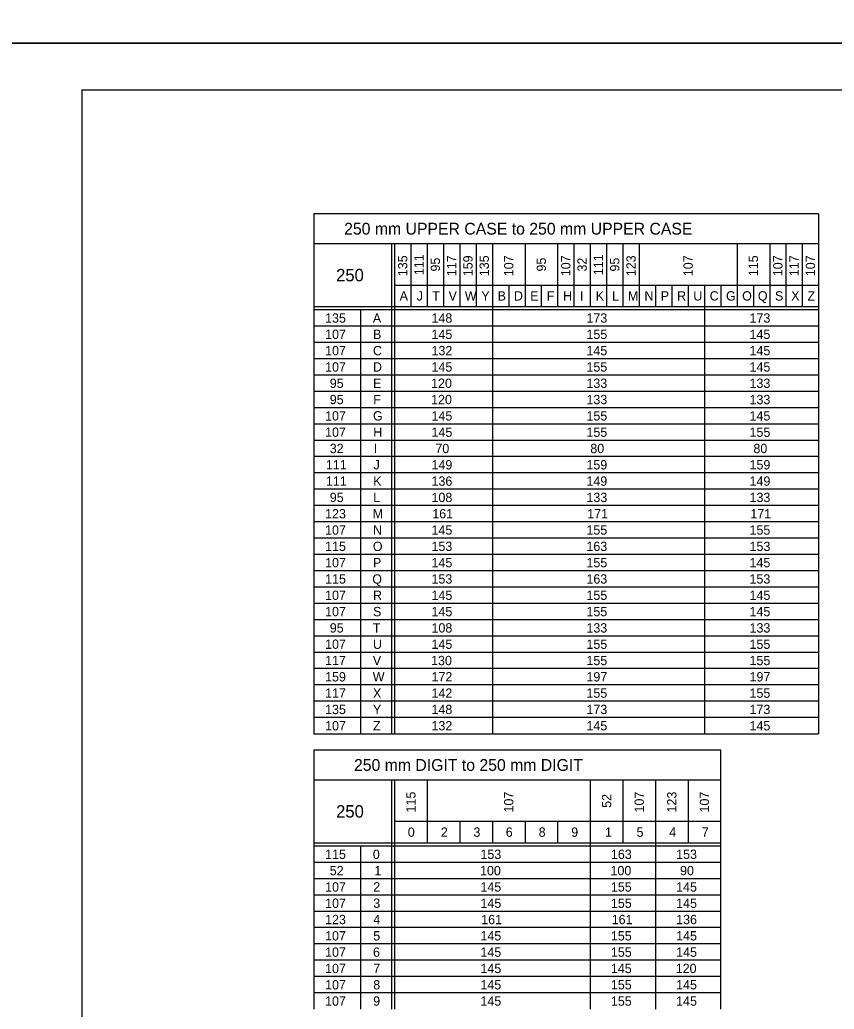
# Model space of a CAD drawing. Extents: x 637580 to 641849, y 297270 to 299646.
# Drawn here: x 638441.3 to 638703.5, y 298146.6 to 298465.1 of the extents above; entities that cross this region are included whole.
import ezdxf

# ---------------------------------------------------------------- set-up
doc = ezdxf.new("R2010")
doc.units = 0
for name, color, linetype in [('1', 7, 'Continuous'), ('2', 7, 'Continuous'), ('XCS-GRID-HVGL', 7, 'Continuous')]:
    doc.layers.add(name, color=color, linetype=linetype)

msp = doc.modelspace()

# ---------------------------------------------------------------- linework, layer by layer
at = {"layer": '1'}
for q in [(639247.31, 298442.63), (638461.31, 297878.63)]:
    msp.add_line((638461.31, 298442.63), q, dxfattribs=at)
at = {"layer": '2'}
for p, q in [((638698.44, 298402.63), (638535.94, 298402.63)), ((638535.94, 298402.63), (638535.94, 298235.25)), ((638698.44, 298402.63), (638698.44, 298235.25)), ((638535.94, 298393.13), (638698.44, 298393.13)), ((638560.94, 298393.13), (638560.94, 298235.25)), ((638561.94, 298393.13), (638561.94, 298235.25)), ((638567.19, 298393.13), (638567.19, 298372.75)), ((638572.44, 298393.13), (638572.44, 298372.75)), ((638577.69, 298393.13), (638577.69, 298372.75)), ((638582.94, 298393.13), (638582.94, 298372.75)), ((638588.19, 298393.13), (638588.19, 298372.75)), ((638593.44, 298393.13), (638593.44, 298235.25)), ((638603.94, 298393.13), (638603.94, 298372.75)), ((638614.44, 298393.13), (638614.44, 298372.75)), ((638619.69, 298393.13), (638619.69, 298372.75)), ((638624.94, 298393.13), (638624.94, 298372.75)), ((638630.19, 298393.13), (638630.19, 298372.75)), ((638635.44, 298393.13), (638635.44, 298372.75)), ((638640.69, 298393.13), (638640.69, 298372.75)), ((638672.19, 298393.13), (638672.19, 298372.75)), ((638682.69, 298393.13), (638682.69, 298372.75)), ((638687.94, 298393.13), (638687.94, 298372.75)), ((638693.19, 298393.13), (638693.19, 298372.75)), ((638561.94, 298379.75), (638698.44, 298379.75)), ((638598.69, 298379.75), (638598.69, 298372.75)), ((638609.19, 298379.75), (638609.19, 298372.75)), ((638645.94, 298379.75), (638645.94, 298372.75)), ((638651.19, 298379.75), (638651.19, 298372.75)), ((638656.44, 298379.75), (638656.44, 298372.75)), ((638656.44, 298379.75), (638656.44, 298372.75)), ((638661.69, 298379.75), (638661.69, 298235.25)), ((638666.94, 298379.75), (638666.94, 298372.75)), ((638677.44, 298379.75), (638677.44, 298372.75)), ((638698.44, 298372.75), (638535.94, 298372.75)), ((638698.44, 298371.75), (638535.94, 298371.75)), ((638550.94, 298371.75), (638550.94, 298235.25)), ((638698.44, 298366.5), (638535.94, 298366.5)), ((638698.44, 298361.25), (638535.94, 298361.25)), ((638698.44, 298356), (638535.94, 298356)), ((638698.44, 298350.75), (638535.94, 298350.75)), ((638698.44, 298345.5), (638535.94, 298345.5)), ((638698.44, 298340.25), (638535.94, 298340.25)), ((638698.44, 298335), (638535.94, 298335)), ((638698.44, 298329.75), (638535.94, 298329.75)), ((638698.44, 298324.5), (638535.94, 298324.5)), ((638698.44, 298319.25), (638535.94, 298319.25)), ((638698.44, 298314), (638535.94, 298314)), ((638698.44, 298308.75), (638535.94, 298308.75)), ((638698.44, 298303.5), (638535.94, 298303.5)), ((638698.44, 298298.25), (638535.94, 298298.25)), ((638698.44, 298293), (638535.94, 298293)), ((638698.44, 298287.75), (638535.94, 298287.75)), ((638698.44, 298282.5), (638535.94, 298282.5)), ((638698.44, 298277.25), (638535.94, 298277.25)), ((638698.44, 298272), (638535.94, 298272)), ((638698.44, 298266.75), (638535.94, 298266.75)), ((638698.44, 298261.5), (638535.94, 298261.5)), ((638698.44, 298256.25), (638535.94, 298256.25)), ((638698.44, 298251), (638535.94, 298251)), ((638698.44, 298245.75), (638535.94, 298245.75)), ((638698.44, 298240.5), (638535.94, 298240.5)), ((638535.94, 298235.25), (638535.94, 298235.25)), ((638535.94, 298235.25), (638698.44, 298235.25)), ((638666.94, 298230), (638535.94, 298230)), ((638535.94, 298230), (638535.94, 298146.63)), ((638666.94, 298146.63), (638666.94, 298230)), ((638535.94, 298220.5), (638666.94, 298220.5)), ((638560.94, 298220.5), (638560.94, 298146.63)), ((638561.94, 298220.5), (638561.94, 298146.63)), ((638572.44, 298220.5), (638572.44, 298200.13)), ((638624.94, 298220.5), (638624.94, 298146.63)), ((638635.44, 298220.5), (638635.44, 298200.13)), ((638645.94, 298220.5), (638645.94, 298146.63)), ((638656.44, 298220.5), (638656.44, 298200.13)), ((638561.94, 298207.13), (638666.94, 298207.13)), ((638582.94, 298207.13), (638582.94, 298200.13)), ((638593.44, 298207.13), (638593.44, 298200.13)), ((638603.94, 298207.13), (638603.94, 298200.13)), ((638614.44, 298207.13), (638614.44, 298200.13)), ((638666.94, 298200.13), (638535.94, 298200.13)), ((638666.94, 298199.13), (638535.94, 298199.13)), ((638550.94, 298199.13), (638550.94, 298146.63)), ((638666.94, 298193.88), (638535.94, 298193.88)), ((638666.94, 298188.63), (638535.94, 298188.63)), ((638666.94, 298183.38), (638535.94, 298183.38)), ((638666.94, 298178.13), (638535.94, 298178.13)), ((638666.94, 298172.88), (638535.94, 298172.88)), ((638666.94, 298167.63), (638535.94, 298167.63)), ((638666.94, 298162.38), (638535.94, 298162.38)), ((638666.94, 298157.13), (638535.94, 298157.13)), ((638666.94, 298151.88), (638535.94, 298151.88))]:
    msp.add_line(p, q, dxfattribs=at)
at = {"layer": 'XCS-GRID-HVGL'}
for points in [[(638421.31, 299051.63), (639262.31, 299051.63), (639262.31, 298457.63), (638421.31, 298457.63)], [(638421.31, 298457.63), (639262.31, 298457.63), (639262.31, 297863.63), (638421.31, 297863.63)]]:
    msp.add_lwpolyline(points, close=True, dxfattribs=at)

# ---------------------------------------------------------------- texts
at = {"layer": '2'}
for s, height, p in [('250 mm UPPER CASE to 250 mm UPPER CASE', 3.8, (638545.72, 298395.98)), ('250', 4, (638543.13, 298380.94)), ('A', 3, (638563.58, 298374.75)), ('J', 3, (638569.07, 298374.75)), ('T', 3, (638574.07, 298374.75)), ('V', 3, (638579.33, 298374.75)), ('W', 3, (638584.56, 298374.75)), ('Y', 3, (638589.87, 298374.75)), ('B', 3, (638595.13, 298374.75)), ('D', 3, (638600.38, 298374.75)), ('E', 3, (638605.64, 298374.75)), ('F', 3, (638610.95, 298374.75)), ('H', 3, (638616.21, 298374.75)), ('I', 3, (638621.63, 298374.75)), ('K', 3, (638626.71, 298374.75)), ('L', 3, (638631.96, 298374.75)), ('M', 3, (638637.06, 298374.75)), ('N', 3, (638642.38, 298374.75)), ('P', 3, (638647.63, 298374.75)), ('R', 3, (638652.88, 298374.75)), ('U', 3, (638658.12, 298374.75)), ('C', 3, (638663.38, 298374.75)), ('G', 3, (638668.63, 298374.75)), ('O', 3, (638673.83, 298374.75)), ('Q', 3, (638678.9, 298374.75)), ('S', 3, (638684.39, 298374.75)), ('X', 3, (638689.62, 298374.75)), ('Z', 3, (638694.88, 298374.75)), ('135', 3, (638539.59, 298367.63)), ('A', 3, (638554.96, 298367.63)), ('148', 3, (638573.84, 298367.63)), ('173', 3, (638623.71, 298367.63)), ('173', 3, (638676.21, 298367.63)), ('107', 3, (638539.59, 298362.38)), ('B', 3, (638555, 298362.38)), ('145', 3, (638573.84, 298362.38)), ('155', 3, (638623.71, 298362.38)), ('145', 3, (638676.21, 298362.38)), ('107', 3, (638539.59, 298357.13)), ('C', 3, (638555, 298357.13)), ('132', 3, (638573.84, 298357.13)), ('145', 3, (638623.71, 298357.13)), ('145', 3, (638676.21, 298357.13)), ('107', 3, (638539.59, 298351.88)), ('D', 3, (638555, 298351.88)), ('145', 3, (638573.84, 298351.88)), ('155', 3, (638623.71, 298351.88)), ('145', 3, (638676.21, 298351.88)), ('95', 3, (638541.09, 298346.63)), ('E', 3, (638555.02, 298346.63)), ('120', 3, (638573.71, 298346.63)), ('133', 3, (638623.71, 298346.63)), ('133', 3, (638676.21, 298346.63)), ('95', 3, (638541.09, 298341.38)), ('F', 3, (638555.07, 298341.38)), ('120', 3, (638573.71, 298341.38)), ('133', 3, (638623.71, 298341.38)), ('133', 3, (638676.21, 298341.38)), ('107', 3, (638539.59, 298336.13)), ('G', 3, (638555, 298336.13)), ('145', 3, (638573.84, 298336.13)), ('155', 3, (638623.71, 298336.13)), ('145', 3, (638676.21, 298336.13)), ('107', 3, (638539.59, 298330.88)), ('H', 3, (638555.09, 298330.88)), ('145', 3, (638573.84, 298330.88)), ('155', 3, (638623.71, 298330.88)), ('155', 3, (638676.21, 298330.88)), ('32', 3, (638541.09, 298325.63)), ('I', 3, (638555.25, 298325.63)), ('70', 3, (638575.09, 298325.63)), ('80', 3, (638624.96, 298325.63)), ('80', 3, (638677.46, 298325.63)), ('111', 3, (638539.84, 298320.38)), ('J', 3, (638555.19, 298320.38)), ('149', 3, (638573.84, 298320.38)), ('159', 3, (638623.71, 298320.38)), ('159', 3, (638676.21, 298320.38)), ('111', 3, (638539.84, 298315.13)), ('K', 3, (638555.09, 298315.13)), ('136', 3, (638573.84, 298315.13)), ('149', 3, (638623.71, 298315.13)), ('149', 3, (638676.21, 298315.13)), ('95', 3, (638541.09, 298309.88)), ('L', 3, (638555.09, 298309.88)), ('108', 3, (638573.84, 298309.88)), ('133', 3, (638623.71, 298309.88)), ('133', 3, (638676.21, 298309.88)), ('123', 3, (638539.59, 298304.63)), ('M', 3, (638554.93, 298304.63)), ('161', 3, (638574.09, 298304.63)), ('171', 3, (638623.96, 298304.63)), ('171', 3, (638676.46, 298304.63)), ('107', 3, (638539.59, 298299.38)), ('N', 3, (638555, 298299.38)), ('145', 3, (638573.84, 298299.38)), ('155', 3, (638623.71, 298299.38)), ('155', 3, (638676.21, 298299.38)), ('115', 3, (638539.59, 298294.13)), ('O', 3, (638554.96, 298294.13)), ('153', 3, (638573.84, 298294.13)), ('163', 3, (638623.71, 298294.13)), ('153', 3, (638676.21, 298294.13)), ('107', 3, (638539.59, 298288.88)), ('P', 3, (638555, 298288.88)), ('145', 3, (638573.84, 298288.88)), ('155', 3, (638623.71, 298288.88)), ('145', 3, (638676.21, 298288.88)), ('115', 3, (638539.59, 298283.63)), ('Q', 3, (638554.78, 298283.63)), ('153', 3, (638573.84, 298283.63)), ('163', 3, (638623.71, 298283.63)), ('153', 3, (638676.21, 298283.63)), ('107', 3, (638539.59, 298278.38)), ('R', 3, (638555, 298278.38)), ('145', 3, (638573.84, 298278.38)), ('155', 3, (638623.71, 298278.38)), ('145', 3, (638676.21, 298278.38)), ('107', 3, (638539.59, 298273.13)), ('S', 3, (638555.02, 298273.13)), ('145', 3, (638573.84, 298273.13)), ('155', 3, (638623.71, 298273.13)), ('145', 3, (638676.21, 298273.13)), ('95', 3, (638541.09, 298267.88)), ('T', 3, (638554.94, 298267.88)), ('108', 3, (638573.84, 298267.88)), ('133', 3, (638623.71, 298267.88)), ('133', 3, (638676.21, 298267.88)), ('107', 3, (638539.59, 298262.63)), ('U', 3, (638554.99, 298262.63)), ('145', 3, (638573.84, 298262.63)), ('155', 3, (638623.71, 298262.63)), ('155', 3, (638676.21, 298262.63)), ('117', 3, (638539.59, 298257.38)), ('V', 3, (638554.96, 298257.38)), ('130', 3, (638573.71, 298257.38)), ('155', 3, (638623.71, 298257.38)), ('155', 3, (638676.21, 298257.38)), ('159', 3, (638539.59, 298252.13)), ('W', 3, (638554.93, 298252.13)), ('172', 3, (638573.84, 298252.13)), ('197', 3, (638623.71, 298252.13)), ('197', 3, (638676.21, 298252.13)), ('117', 3, (638539.59, 298246.88)), ('X', 3, (638554.99, 298246.88)), ('142', 3, (638573.84, 298246.88)), ('155', 3, (638623.71, 298246.88)), ('155', 3, (638676.21, 298246.88)), ('135', 3, (638539.59, 298241.63)), ('Y', 3, (638554.99, 298241.63)), ('148', 3, (638573.84, 298241.63)), ('173', 3, (638623.71, 298241.63)), ('173', 3, (638676.21, 298241.63)), ('107', 3, (638539.59, 298236.38)), ('Z', 3, (638555, 298236.38)), ('132', 3, (638573.84, 298236.38)), ('145', 3, (638623.71, 298236.38)), ('145', 3, (638676.21, 298236.38)), ('250 mm DIGIT to 250 mm DIGIT', 3.8, (638548.88, 298223.35)), ('250', 4, (638543.13, 298208.31)), ('0', 3, (638566.21, 298202.13)), ('2', 3, (638576.84, 298202.13)), ('3', 3, (638587.34, 298202.13)), ('6', 3, (638597.75, 298202.13)), ('8', 3, (638608.34, 298202.13)), ('9', 3, (638618.82, 298202.13)), ('1', 3, (638629.68, 298202.13)), ('5', 3, (638639.84, 298202.13)), ('4', 3, (638650.34, 298202.13)), ('7', 3, (638660.84, 298202.13)), ('115', 3, (638539.59, 298195)), ('0', 3, (638554.96, 298195)), ('153', 3, (638589.59, 298195)), ('163', 3, (638631.59, 298195)), ('153', 3, (638652.59, 298195)), ('52', 3, (638541.09, 298189.75)), ('1', 3, (638555.43, 298189.75)), ('100', 3, (638589.46, 298189.75)), ('100', 3, (638631.46, 298189.75)), ('90', 3, (638653.84, 298189.75)), ('107', 3, (638539.59, 298184.5)), ('2', 3, (638555.09, 298184.5)), ('145', 3, (638589.59, 298184.5)), ('155', 3, (638631.59, 298184.5)), ('145', 3, (638652.59, 298184.5)), ('107', 3, (638539.59, 298179.25)), ('3', 3, (638555.09, 298179.25)), ('145', 3, (638589.59, 298179.25)), ('155', 3, (638631.59, 298179.25)), ('145', 3, (638652.59, 298179.25)), ('123', 3, (638539.59, 298174)), ('4', 3, (638555.09, 298174)), ('161', 3, (638589.84, 298174)), ('161', 3, (638631.84, 298174)), ('136', 3, (638652.59, 298174)), ('107', 3, (638539.59, 298168.75)), ('5', 3, (638555.09, 298168.75)), ('145', 3, (638589.59, 298168.75)), ('155', 3, (638631.59, 298168.75)), ('145', 3, (638652.59, 298168.75)), ('107', 3, (638539.59, 298163.5)), ('6', 3, (638555, 298163.5)), ('145', 3, (638589.59, 298163.5)), ('155', 3, (638631.59, 298163.5)), ('145', 3, (638652.59, 298163.5)), ('107', 3, (638539.59, 298158.25)), ('7', 3, (638555.09, 298158.25)), ('145', 3, (638589.59, 298158.25)), ('145', 3, (638631.59, 298158.25)), ('120', 3, (638652.46, 298158.25)), ('107', 3, (638539.59, 298153)), ('8', 3, (638555.09, 298153)), ('145', 3, (638589.59, 298153)), ('155', 3, (638631.59, 298153)), ('145', 3, (638652.59, 298153)), ('107', 3, (638539.59, 298147.75)), ('9', 3, (638555.07, 298147.75)), ('145', 3, (638589.59, 298147.75)), ('155', 3, (638631.59, 298147.75)), ('145', 3, (638652.59, 298147.75))]:
    msp.add_text(s, height=height, dxfattribs=at).set_placement(p)
for s, p in [('135', (638566.06, 298382.59)), ('111', (638571.31, 298382.93)), ('95', (638576.56, 298384.09)), ('117', (638581.81, 298382.59)), ('159', (638587.06, 298382.58)), ('135', (638592.31, 298382.59)), ('107', (638600.19, 298382.59)), ('95', (638610.69, 298384.09)), ('107', (638618.56, 298382.59)), ('32', (638623.81, 298384.09)), ('111', (638629.06, 298382.93)), ('95', (638634.31, 298384.09)), ('123', (638639.56, 298382.59)), ('107', (638657.94, 298382.59)), ('115', (638678.94, 298382.59)), ('107', (638686.81, 298382.59)), ('117', (638692.06, 298382.59)), ('107', (638697.31, 298382.59)), ('115', (638568.69, 298209.96)), ('107', (638600.19, 298209.96)), ('52', (638631.69, 298211.46)), ('107', (638642.19, 298209.96)), ('123', (638652.69, 298209.96)), ('107', (638663.19, 298209.96))]:
    msp.add_text(s, height=3, rotation=90, dxfattribs=at).set_placement(p)

doc.saveas('drawing.dxf')
